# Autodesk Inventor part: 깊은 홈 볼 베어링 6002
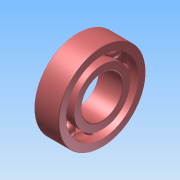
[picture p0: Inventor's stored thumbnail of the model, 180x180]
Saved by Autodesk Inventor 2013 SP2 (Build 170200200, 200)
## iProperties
Created: 2025-10
Part Number: 깊은 홈 볼 베어링 6002
Material: Generic
Document SubType Name: Modeling
Designer: 601
Density: 1 g/cm^3
Author: 601
변환 표준: STEP AP214IS
전처리기: Build: 200, Release: 2013 SP2 Update 6 - Date: Thu 07/17/2014
전송 단위: 밀리미터
불확실성: 0.01
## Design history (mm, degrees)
node "깊은 홈 볼 베어링 60021"
body "Solid1"
node "Solid1_1"
node "Solid1_2"
node "Solid1_3"
node "Solid1_4"
node "Solid1_5"
node "Solid1_6"
node "Solid1_7"
node "Solid1_8"
node "Solid1_9"
node "기준1"
node "기준2"
node "기준3"
node "기준4"
node "기준5"
node "기준6"
node "기준7"
node "기준8"
node "기준9"
node "기준10"
